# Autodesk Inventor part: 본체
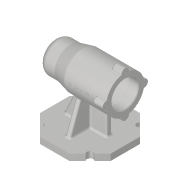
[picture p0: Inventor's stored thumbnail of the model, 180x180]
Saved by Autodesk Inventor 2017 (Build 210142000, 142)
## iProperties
Created: 2019-12
Part Number: 본체
Material: 알루미늄 6061
Document SubType Name: Modeling
Designer: 5-14-le
Density: 2.7 g/cm^3
Appearance: 알루미늄 - 평지
Mass: 725.805 g
Surface Area: 714.68 cm^2
Volume: 268.817 cm^3
Author: 5-14-le
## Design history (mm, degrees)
sketch "스케치2" dims "d0" = 112
  geometry: L1 (-23.196, -56)-(-56, -23.196); L2 (-56, -23.196)-(-56, 23.196); L3 (-56, 23.196)-(-23.196, 56); L4 (-23.196, 56)-(23.196, 56); L5 (23.196, 56)-(56, 23.196); L6 (56, 23.196)-(56, -23.196); L7 (56, -23.196)-(23.196, -56); L8 (23.196, -56)-(-23.196, -56); L9 (78.4, 0)-(-78.4, 0) reference; 4 further points
  constraints: 16 end point, 2 coincident, 1 midpoint, 1 parallel, 1 vertical alignment, 19 other
extrude "돌출1" new body sketch "스케치2" distance "d1" = 10; taper "d2" = 0 deg
sketch "스케치3"
  geometry: L1 (56, 23.196)-(23.196, 56) reference; L2 (-23.196, 56)-(-56, 23.196) reference; L3 (-56, -23.196)-(-23.196, -56) reference; L4 (23.196, -56)-(56, -23.196) reference; L5 (-39.598, 39.598)-(39.598, -39.598); L6 (39.598, 39.598)-(-39.598, -39.598); L7 (-78.4, 0)-(78.4, 0) reference; C1 r 5 at (-39.598, 39.598); C2 r 5 at (39.598, 39.598); C3 r 5 at (39.598, -39.598); C4 r 5 at (-39.598, -39.598); 1 further point
  constraints: 4 centre point, 4 coincident, 4 end point, 4 midpoint, 3 equal radius
  dimensions: "d3" = 10 diameter of C1
extrude "돌출2" cut sketch "스케치3" stored distance "d4" = 10; taper "d5" = 0 deg
sketch "스케치4"
  geometry: L1 (56, 80)-(-56, 80); L2 (-56, 80)-(-56, 105); L3 (56, 110)-(56, 80); L4 (56, 110)-(-11, 110); L5 (-11, 110)-(-31, 105); L6 (-31, 105)-(-56, 105); L7 (-23.196, 0)-(23.196, 0) reference; L8 (56, 0)-(56, 10) reference; L9 (56, 101)-(41, 101); L10 (41, 101)-(41, 104); L11 (41, 104)-(-13, 104); L12 (-13, 104)-(-13, 101); L13 (-13, 101)-(-25, 101); L14 (-25, 101)-(-25, 97.5); L15 (-25, 97.5)-(-43, 97.5); L16 (-43, 97.5)-(-43, 96); L17 (-43, 96)-(-47, 96); L18 (-47, 96)-(-47, 90.5); L19 (-47, 90.5)-(-50, 90.5); L20 (-50, 90.5)-(-50, 80); 1 further point
  constraints: 36 end point, 12 perpendicular, 4 point on line, 3 horizontal, 1 collinear, 1 parallel
  dimensions: "d8" = 80 distance between parallel lines of L1 L7; "d9" = 60 diameter of L4 L1; "d10" = 112 distance between parallel lines of L3 L2; "d11" = 45 distance from line of L2 L4.end; "d12" = 25 distance of L5.end L2.end; "d13" = 50 diameter of L6 L1; "d14" = 3 distance of L18.end L19.end; "d15" = 4 distance of L16.end L17.end; "d16" = 18 distance of L14.end L15.end; "d17" = 12 distance of L12.end L13.end; "d18" = 15 distance of L9.start L9.end; "d19" = 54 distance of L10.end L11.end; "d20" = 42 diameter of L9 L1; "d21" = 48 diameter of L11 L1; "d22" = 35 diameter of L15 L1; "d23" = 32 diameter of L17 L1; "d24" = 21 diameter of L19 L1
revolve "회전1" sketch "스케치4" stored, may be unused: angle "d25" = 90 deg
sketch "스케치5"
  geometry: L1 (56, 110)-(40, 110); L2 (40, 110)-(40, 116); L3 (40, 116)-(56, 116); L4 (56, 116)-(56, 110); L5 (-11, 110)-(56, 110) reference; 1 further point
  constraints: 8 end point, 2 parallel, 1 horizontal, 1 perpendicular
  dimensions: "d26" = 16 distance of L2.end L3.end; "d27" = 6 distance of L3.end L1.start
revolve "회전2" sketch "스케치5" stored, may be unused: angle "d28" = 90 deg
sketch "스케치6"
  geometry: A1 r 6 centre (0, 0) between (5.97, -0.6) and (-5.97, -0.6) reference; A2 r 6 centre (-30, -30) between (-29.4, -24.03) and (-29.4, -35.97) reference; A3 r 6 centre (0, -60) between (-5.97, -59.4) and (5.97, -59.4) reference; A4 r 6 centre (30, -30) between (29.4, -35.97) and (29.4, -24.03) reference; 5 further points
  constraints: 4 coincident
hole "구멍1" sketch "스케치6" at (-30, -30), (0, -60), (30, -30), (0, 0) diameter "d32" = 3.242; stored, may be unused: countersink angle "d36" = 90 deg, drill point angle "d38" = 118 deg; dims "d33" = 8, "d34" = 4, "d35" = 2, "d37" = 11
sketch "스케치7"
  geometry: L1 (-38, 10)-(-17.018, 54.997); L2 (-17.018, 54.997)-(31, 54.997); L3 (-43.134, 10)-(-56, 10) reference; L4 (31, 54.997)-(31, 10); L5 (31, 10)-(-38, 10); L6 (36.062, 10)-(36.062, 0) reference; L7 (-56, 0)-(-56, 10) reference; L8 (56, 0)-(56, 10) reference; L9 (23.196, 10)-(-23.196, 10) reference; 1 further point
  constraints: 8 end point, 2 perpendicular, 1 collinear, 1 parallel
  dimensions: "d39" = 115 deg angle of L3 L1; "d40" = 18 distance from line of L7 L1.start; "d41" = 25 distance between parallel lines of L8 L4; "d42" = 48.01752 distance of L1.end L2.end
extrude "돌출3" join sketch "스케치7" stored distance "d43" = 8; taper "d44" = 0 deg
sketch "스케치8"
  geometry: L1 (56.766, 18.979)-(10, 36); L2 (0, 56)-(10, 56) reference; L3 (10, 43.134)-(10, 56) reference; A1 r 30 centre (80, 0) between (50.268, -4) and (50.268, 4) reference; 1 further point
  constraints: 2 end point, 1 point on circle, 1 point on line
  dimensions: "d45" = 20 distance from line of L2 L1.end; "d46" = 110 deg angle of L3 L1
feature "리브1" sketch "스케치8" dims "d47" = 1, "d48" = 8, "d49" = 0, "d50" = 0, "d51" = 1, "d52" = 1
fillet "모깎기1" dims "d53" = 3
chamfer "모따기1" distance "d54" = 1; stored, may be unused: second distance "d55" = 2, angle "d56" = 45 deg
fillet "모깎기2" dims "d57" = 0.3
fillet "모깎기3" dims "d58" = 10
fillet "모깎기4" dims "d59" = 3
fillet "모깎기5" dims "d60" = 1
fillet "모깎기6" dims "d61" = 3
node "작업 평면1"
sketch "스케치9"
  geometry: L1 (-5.739, 83.002)-(35.739, 83.002); L2 (35.739, 83.002)-(35.739, 76.998); L3 (35.739, 76.998)-(-5.739, 76.998); L4 (-5.739, 76.998)-(-5.739, 83.002); L5 (35.739, 80)-(-5.739, 80); L6 (15, 83.002)-(15, 80); L7 (-10.631, 110)-(39, 110) reference; L8 (56, 110.171)-(56, 116) reference; 1 further point
  constraints: 4 end point, 4 midpoint, 2 other
  dimensions: "d63" = 30 distance from line of L7 L6.end; "d64" = 41 distance from line of L8 L6.end
feature "엠보싱1" sketch "스케치9" dims "d0" = 112, "d65" = 0.5, "d66" = 0
node "솔리드1"
pattern_circular "원형 패턴1" dims angle "d30" = 360 deg
mirror "미러1"
other parameters: "d62" = 30.5
